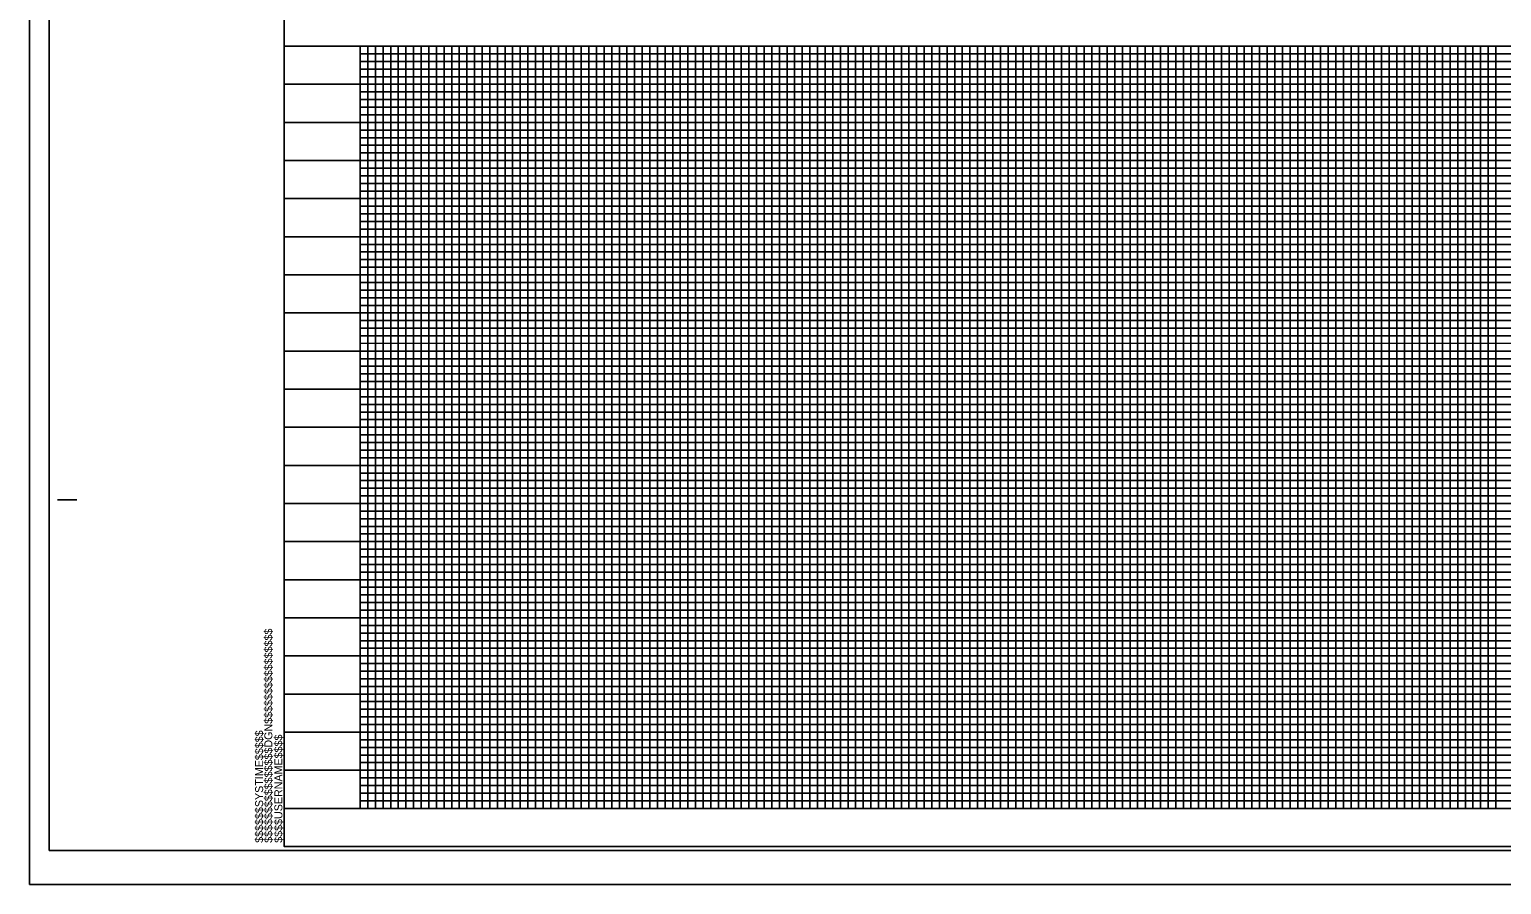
# Model space of a CAD drawing. Extents: x 1648862 to 1650739, y 844691 to 845791.
# Drawn here: x 1648862 to 1649828, y 844691 to 845252 of the extents above; entities that cross this region are included whole.
import ezdxf

# ---------------------------------------------------------------- set-up
doc = ezdxf.new("R2010")
doc.units = 0
for name, color, linetype in [('Prop Conc Barrier Transition Section', 7, 'Continuous'), ('Prop Conc Barrier Variable Height', 7, 'Continuous'), ('Prop Conc Expressway Gutter', 7, 'Continuous'), ('Prop DGN Element Guardrail', 7, 'Continuous'), ('Prop Dimension', 7, 'Continuous'), ('Prop Dimension Text', 7, 'Continuous'), ('Prop Easement Construction', 7, 'Continuous'), ('Prop Easement Construction Station Offsets', 7, 'Continuous')]:
    doc.layers.add(name, color=color, linetype=linetype)

msp = doc.modelspace()

# ---------------------------------------------------------------- linework, layer by layer
at = {"layer": 'Prop Conc Barrier Transition Section'}
msp.add_lwpolyline([(1648862.28, 844691.02), (1650546.28, 844691.02), (1650546.28, 845791.02), (1648862.28, 845791.02)], close=True, dxfattribs=at)
at = {"layer": 'Prop Conc Barrier Variable Height'}
msp.add_lwpolyline([(1649079.28, 845241.02), (1650479.28, 845241.02), (1650479.28, 844741.02), (1649079.28, 844741.02)], close=True, dxfattribs=at)
at = {"layer": 'Prop Conc Expressway Gutter'}
for p, q in [((1649079.28, 845236.02), (1650479.28, 845236.02)), ((1650479.28, 845231.02), (1649079.28, 845231.02)), ((1649079.28, 845226.02), (1650479.28, 845226.02)), ((1650479.28, 845221.02), (1649079.28, 845221.02)), ((1649079.28, 845211.02), (1650479.28, 845211.02)), ((1650479.28, 845206.02), (1649079.28, 845206.02)), ((1649079.28, 845201.02), (1650479.28, 845201.02)), ((1650479.28, 845196.02), (1649079.28, 845196.02)), ((1649079.28, 845186.02), (1650479.28, 845186.02)), ((1650479.28, 845181.02), (1649079.28, 845181.02)), ((1649079.28, 845176.02), (1650479.28, 845176.02)), ((1650479.28, 845171.02), (1649079.28, 845171.02)), ((1649079.28, 845161.02), (1650479.28, 845161.02)), ((1650479.28, 845156.02), (1649079.28, 845156.02)), ((1649079.28, 845151.02), (1650479.28, 845151.02)), ((1650479.28, 845146.02), (1649079.28, 845146.02)), ((1649079.28, 845136.02), (1650479.28, 845136.02)), ((1650479.28, 845131.02), (1649079.28, 845131.02)), ((1649079.28, 845126.02), (1650479.28, 845126.02)), ((1650479.28, 845121.02), (1649079.28, 845121.02)), ((1649079.28, 845111.02), (1650479.28, 845111.02)), ((1650479.28, 845106.02), (1649079.28, 845106.02)), ((1649079.28, 845101.02), (1650479.28, 845101.02)), ((1650479.28, 845096.02), (1649079.28, 845096.02)), ((1649079.28, 845086.02), (1650479.28, 845086.02)), ((1650479.28, 845081.02), (1649079.28, 845081.02)), ((1649079.28, 845076.02), (1650479.28, 845076.02)), ((1650479.28, 845071.02), (1649079.28, 845071.02)), ((1649079.28, 845061.02), (1650479.28, 845061.02)), ((1650479.28, 845056.02), (1649079.28, 845056.02)), ((1649079.28, 845051.02), (1650479.28, 845051.02)), ((1650479.28, 845046.02), (1649079.28, 845046.17)), ((1649079.28, 845036.02), (1650479.28, 845036.02)), ((1650479.28, 845031.02), (1649079.28, 845031.02)), ((1649079.28, 845026.02), (1650479.28, 845026.02)), ((1650479.28, 845021.02), (1649079.28, 845021.02)), ((1649079.28, 845011.02), (1650479.28, 845011.02)), ((1650479.28, 845006.02), (1649079.28, 845006.02)), ((1649079.28, 845001.02), (1650479.28, 845001.02)), ((1650479.28, 844996.02), (1649079.28, 844996.02)), ((1649079.28, 844986.02), (1650479.28, 844986.02)), ((1650479.28, 844981.02), (1649079.28, 844981.02)), ((1649079.28, 844976.02), (1650479.28, 844976.02)), ((1650479.28, 844971.02), (1649079.28, 844971.02)), ((1649079.28, 844961.02), (1650479.28, 844961.02)), ((1650479.28, 844956.02), (1649079.28, 844956.02)), ((1649079.28, 844951.02), (1650479.28, 844951.02)), ((1650479.28, 844946.02), (1649079.28, 844946.02)), ((1649079.28, 844936.02), (1650479.28, 844936.02)), ((1650479.28, 844931.02), (1649079.28, 844931.02)), ((1649079.28, 844926.02), (1650479.28, 844926.02)), ((1650479.28, 844921.02), (1649079.28, 844921.02)), ((1649079.28, 844911.02), (1650479.28, 844911.02)), ((1650479.28, 844906.02), (1649079.28, 844906.02)), ((1649079.28, 844901.02), (1650479.28, 844901.02)), ((1650479.28, 844896.02), (1649079.28, 844896.02)), ((1649079.28, 844886.02), (1650479.28, 844886.02)), ((1650479.28, 844881.02), (1649079.28, 844881.02)), ((1649079.28, 844876.02), (1650479.28, 844876.02)), ((1650479.28, 844871.02), (1649079.28, 844871.02)), ((1649079.28, 844861.02), (1650479.28, 844861.02)), ((1650479.28, 844856.02), (1649079.28, 844856.02)), ((1649079.28, 844851.02), (1650479.28, 844851.02)), ((1650479.28, 844846.02), (1649079.28, 844846.02)), ((1649079.28, 844836.02), (1650479.28, 844836.02)), ((1650479.28, 844831.02), (1649079.28, 844831.02)), ((1649079.28, 844826.02), (1650479.28, 844826.02)), ((1650479.28, 844821.02), (1649079.28, 844821.02)), ((1649079.28, 844811.02), (1650479.28, 844811.02)), ((1650479.28, 844806.02), (1649079.28, 844806.02)), ((1649079.28, 844801.02), (1650479.28, 844801.02)), ((1650479.28, 844796.02), (1649079.28, 844796.02)), ((1649079.28, 844786.02), (1650479.28, 844786.02)), ((1650479.28, 844781.02), (1649079.28, 844781.02)), ((1649079.28, 844776.02), (1650479.28, 844776.02)), ((1650479.28, 844771.02), (1649079.28, 844771.02)), ((1649079.28, 844761.02), (1650479.28, 844761.02)), ((1650479.28, 844756.02), (1649079.28, 844756.02)), ((1649079.28, 844751.02), (1650479.28, 844751.02)), ((1649079.28, 844746.02), (1650479.28, 844746.02))]:
    msp.add_line(p, q, dxfattribs=at)
for points in [[(1649079.28, 845241.02), (1649084.28, 845241.02), (1649084.28, 844741.02), (1649089.28, 844741.02), (1649089.28, 845241.02), (1649094.28, 845241.02), (1649094.28, 844741.02), (1649099.28, 844741.02), (1649099.28, 845241.02), (1649109.28, 845241.02), (1649109.28, 844741.02), (1649114.28, 844741.02), (1649114.28, 845241.02), (1649119.28, 845241.02), (1649119.28, 844741.02), (1649124.28, 844741.02), (1649134.28, 844741.02), (1649139.28, 844741.02), (1649139.28, 845241.02), (1649144.28, 845241.02), (1649144.28, 844741.02), (1649149.28, 844741.02), (1649149.28, 845241.02), (1649159.28, 845241.02), (1649159.28, 844741.02), (1649164.28, 844741.02), (1649164.28, 845241.02), (1649169.28, 845241.02), (1649169.28, 844741.02), (1649174.28, 844741.02), (1649174.28, 845241.02), (1649184.28, 845241.02), (1649184.28, 844741.02), (1649189.28, 844741.02), (1649189.28, 845241.02), (1649194.28, 845241.02), (1649194.28, 844741.02), (1649199.28, 844741.02), (1649199.28, 845241.02), (1649209.28, 845241.02), (1649209.28, 844741.02), (1649214.28, 844741.02), (1649214.28, 845241.02), (1649219.28, 845241.02), (1649219.28, 844741.02), (1649224.28, 844741.02), (1649224.28, 845241.02), (1649234.28, 845241.02), (1649234.28, 844741.02), (1649239.28, 844741.02), (1649239.28, 845241.02), (1649244.28, 845241.02), (1649244.28, 844741.02), (1649249.28, 844741.02), (1649249.28, 845241.02), (1649259.28, 845241.02), (1649259.28, 844741.02), (1649264.28, 844741.02), (1649264.28, 845241.02), (1649269.28, 845241.02), (1649269.28, 844741.02), (1649274.28, 844741.02), (1649274.28, 845241.02), (1649284.28, 845241.02), (1649284.28, 844741.02), (1649289.28, 844741.02), (1649289.28, 845241.02), (1649294.28, 845241.02), (1649294.28, 844741.02)], [(1649124.28, 844741.02), (1649124.28, 845241.02), (1649134.28, 845241.02), (1649134.28, 844741.02)], [(1649294.28, 844741.02), (1649299.28, 844741.02), (1649299.28, 845241.02), (1649309.28, 845241.02), (1649309.28, 844741.02), (1649314.28, 844741.02), (1649314.28, 845241.02), (1649319.28, 845241.02), (1649319.28, 844741.02), (1649324.28, 844741.02), (1649324.28, 845241.02), (1649334.28, 845241.02), (1649334.28, 844741.02), (1649339.28, 844741.02), (1649339.28, 845241.02), (1649344.28, 845241.02), (1649344.28, 844741.02), (1649349.28, 844741.02), (1649349.28, 845241.02), (1649359.28, 845241.02), (1649359.28, 844741.02), (1649364.28, 844741.02), (1649364.28, 845241.02), (1649369.28, 845241.02), (1649369.28, 844741.02), (1649374.28, 844741.02), (1649374.28, 845241.02), (1649384.28, 845241.02), (1649384.28, 844741.02), (1649389.28, 844741.02), (1649389.28, 845241.02), (1649394.28, 845241.02), (1649394.28, 844741.02), (1649399.28, 844741.02), (1649399.28, 845241.02), (1649409.28, 845241.02), (1649409.28, 844741.02), (1649414.28, 844741.02), (1649414.28, 845241.02), (1649419.28, 845241.02), (1649419.28, 844741.02), (1649424.28, 844741.02), (1649424.28, 845241.02), (1649434.28, 845241.02), (1649434.28, 844741.02), (1649439.28, 844741.02), (1649439.28, 845241.02), (1649444.28, 845241.02), (1649444.28, 844741.02), (1649449.28, 844741.02), (1649449.28, 845241.02), (1649459.28, 845241.02), (1649459.28, 844741.02), (1649464.28, 844741.02), (1649464.28, 845241.02), (1649469.28, 845241.02), (1649469.28, 844741.02), (1649474.28, 844741.02), (1649474.28, 845241.02), (1649484.28, 845241.02), (1649484.28, 844741.02), (1649489.28, 844741.02), (1649489.28, 845241.02), (1649494.28, 845241.02), (1649494.28, 844741.02), (1649499.28, 844741.02), (1649499.28, 845241.02), (1649509.28, 845241.02), (1649509.28, 844741.02), (1649514.28, 844741.02), (1649514.28, 845241.02), (1649519.28, 845241.02), (1649519.28, 844741.02), (1649524.28, 844741.02), (1649524.28, 845241.02), (1649534.28, 845241.02), (1649534.28, 844741.02), (1649539.28, 844741.02), (1649539.28, 845241.02), (1649544.28, 845241.02), (1649544.28, 844741.02), (1649549.28, 844741.02), (1649549.28, 845241.02), (1649559.28, 845241.02), (1649559.28, 844741.02), (1649564.28, 844741.02), (1649564.28, 845241.02), (1649569.28, 845241.02), (1649569.28, 844741.02), (1649574.28, 844741.02), (1649574.28, 845241.02), (1649584.28, 845241.02), (1649584.28, 844741.02), (1649589.28, 844741.02), (1649589.28, 845241.02), (1649594.28, 845241.02), (1649594.28, 844741.02), (1649599.28, 844741.02), (1649599.28, 845241.02), (1649609.28, 845241.02)], [(1649609.28, 845241.02), (1649609.28, 844741.02), (1649614.28, 844741.02), (1649614.28, 845241.02), (1649619.28, 845241.02), (1649619.28, 844741.02), (1649624.28, 844741.02), (1649624.28, 845241.02), (1649634.28, 845241.02), (1649634.28, 844741.02), (1649639.28, 844741.02), (1649639.28, 845241.02), (1649644.28, 845241.02), (1649644.28, 844741.02), (1649649.28, 844741.02), (1649649.28, 845241.02), (1649659.28, 845241.02), (1649659.28, 844741.02), (1649664.28, 844741.02), (1649664.28, 845241.02), (1649669.28, 845241.02), (1649669.28, 844741.02), (1649674.28, 844741.02), (1649674.28, 845241.02), (1649684.28, 845241.02), (1649684.28, 844741.02), (1649689.28, 844741.02), (1649689.28, 845241.02), (1649694.28, 845241.02), (1649694.28, 844741.02), (1649699.28, 844741.02), (1649699.28, 845241.02), (1649709.28, 845241.02), (1649709.28, 844741.02), (1649714.28, 844741.02), (1649714.28, 845241.02), (1649719.28, 845241.02), (1649719.28, 844741.02), (1649724.28, 844741.02), (1649724.28, 845241.02), (1649734.28, 845241.02), (1649734.28, 844741.02), (1649734.28, 844741.02), (1649739.28, 844741.02), (1649739.28, 845241.02), (1649744.28, 845241.02), (1649744.28, 844741.02), (1649749.28, 844741.02), (1649749.28, 845241.02), (1649759.28, 845241.02), (1649759.28, 844741.02), (1649764.28, 844741.02), (1649764.28, 845241.02), (1649769.28, 845241.02), (1649769.28, 844741.02), (1649774.28, 844741.02), (1649774.28, 845241.02), (1649784.28, 845241.02), (1649784.28, 844741.02), (1649789.28, 844741.02), (1649789.28, 845241.02), (1649794.28, 845241.02), (1649794.28, 844741.02), (1649799.28, 844741.02), (1649799.28, 845241.02), (1649809.28, 845241.02), (1649809.28, 844741.02), (1649814.28, 844741.02), (1649814.28, 845241.02), (1649819.28, 845241.02), (1649819.28, 844741.02), (1649824.28, 844741.02), (1649824.28, 845241.02), (1649834.28, 845241.02)]]:
    msp.add_lwpolyline(points, dxfattribs=at)
at = {"layer": 'Prop DGN Element Guardrail'}
for p, q in [((1649029.28, 845241.02), (1650529.28, 845241.02)), ((1648880.78, 844943.52), (1648893.28, 844943.52)), ((1650529.28, 844741.02), (1649029.28, 844741.02)), ((1649029.28, 844716.02), (1650529.28, 844716.02)), ((1649029.28, 844716.02), (1649029.28, 844716.02)), ((1649029.28, 844716.02), (1649029.28, 844716.02)), ((1649029.28, 844716.02), (1649029.28, 844716.02)), ((1649029.28, 844716.02), (1649029.28, 844716.02)), ((1649029.28, 844716.02), (1649029.28, 844716.02)), ((1649029.28, 844716.02), (1649029.28, 844716.02)), ((1649029.28, 844716.02), (1649029.28, 844716.02))]:
    msp.add_line(p, q, dxfattribs=at)
msp.add_lwpolyline([(1650529.28, 845766.02), (1649029.28, 845766.02), (1649029.28, 844716.02), (1650529.28, 844716.02)], close=True, dxfattribs=at)
msp.add_lwpolyline([(1649066.78, 844716.02), (1649066.78, 844716.02)], dxfattribs=at)
at = {"layer": 'Prop Dimension'}
for p, q in [((1649529.28, 845241.02), (1649579.28, 845241.02)), ((1649629.28, 845241.02), (1649679.28, 845241.02)), ((1649729.28, 845241.02), (1649779.28, 845241.02)), ((1649029.28, 844741.02), (1649029.28, 844741.02))]:
    msp.add_line(p, q, dxfattribs=at)
for points in [[(1649079.28, 845241.02), (1649079.28, 844741.02), (1649129.28, 844741.02), (1649129.28, 845241.02), (1649179.28, 845241.02), (1649179.28, 844741.02), (1649229.28, 844741.02), (1649229.28, 845241.02), (1649279.28, 845241.02), (1649279.28, 844741.02), (1649329.28, 844741.02), (1649329.28, 845241.02), (1649379.28, 845241.02), (1649379.28, 844741.02), (1649429.28, 844741.02), (1649429.28, 845241.02), (1649479.28, 845241.02), (1649479.28, 844741.02), (1649529.28, 844741.02), (1649529.28, 845241.02), (1649579.28, 845241.02), (1649579.28, 844741.02), (1649629.28, 844741.02), (1649629.28, 845241.02), (1649679.28, 845241.02), (1649679.28, 844741.02), (1649729.28, 844741.02), (1649729.28, 845241.02), (1649779.28, 845241.02), (1649779.28, 844741.02), (1649829.28, 844741.02)], [(1650529.28, 845191.02), (1649029.28, 845191.02)], [(1650529.28, 845141.02), (1649029.28, 845141.02), (1649029.28, 845091.02), (1650529.28, 845091.02)], [(1650529.28, 845041.02), (1649029.28, 845041.02), (1649029.28, 844991.02), (1650529.28, 844991.02)], [(1650529.28, 844941.02), (1649029.28, 844941.02), (1649029.28, 844891.02), (1650529.28, 844891.02)], [(1650529.28, 844841.02), (1649029.28, 844841.02), (1649029.28, 844841.02), (1649029.28, 844791.02), (1650529.28, 844791.02)], [(1650529.28, 844741.02), (1649029.28, 844741.02)]]:
    msp.add_lwpolyline(points, dxfattribs=at)
at = {"layer": 'Prop Dimension Text'}
for points in [[(1649054.28, 845241.02), (1649104.28, 845241.02), (1649104.28, 844741.02), (1649154.28, 844741.02), (1649154.28, 845241.02), (1649204.28, 845241.02), (1649204.28, 844741.02), (1649254.28, 844741.02), (1649254.28, 845241.02), (1649304.28, 845241.02), (1649304.28, 844741.02), (1649354.28, 844741.02), (1649354.28, 845241.02), (1649404.28, 845241.02), (1649404.28, 844741.02), (1649454.28, 844741.02), (1649454.28, 845241.02), (1649504.28, 845241.02), (1649504.28, 844741.02), (1649554.28, 844741.02), (1649554.28, 845241.02), (1649604.28, 845241.02), (1649604.28, 844741.02), (1649654.28, 844741.02), (1649654.28, 844741.02), (1649654.28, 845241.02), (1649704.28, 845241.02), (1649704.28, 844741.02), (1649754.28, 844741.02), (1649754.28, 845241.02), (1649804.28, 845241.02), (1649804.28, 844741.02), (1649854.28, 844741.02)], [(1649029.28, 845216.02), (1650529.28, 845216.02)], [(1650529.28, 845166.02), (1649029.28, 845166.02), (1649029.28, 845116.02), (1650529.28, 845116.02)], [(1650529.28, 845066.02), (1649029.28, 845066.02), (1649029.28, 845016.02), (1650529.28, 845016.02)], [(1650529.28, 844966.02), (1649029.28, 844966.02), (1649029.28, 844916.02), (1650529.28, 844916.02)], [(1650529.28, 844866.02), (1649029.28, 844866.02), (1649029.28, 844816.02), (1650529.28, 844816.02)], [(1650529.28, 844766.02), (1649029.28, 844766.02)]]:
    msp.add_lwpolyline(points, dxfattribs=at)
at = {"layer": 'Prop Easement Construction'}
msp.add_lwpolyline([(1648875.28, 844713.47), (1650541.78, 844713.47), (1650541.78, 845768.57), (1648875.28, 845768.57)], close=True, dxfattribs=at)
at = {"layer": 'Prop Easement Construction Station Offsets'}
for p, q in [((1649029.28, 845241.02), (1650529.17, 845241.02)), ((1649079.28, 845241.02), (1649079.28, 844741.02)), ((1649129.28, 845241.02), (1649129.28, 844741.02)), ((1649179.28, 845241.02), (1649179.28, 844741.02)), ((1649229.28, 845241.02), (1649229.28, 844741.02)), ((1649279.28, 845241.02), (1649279.28, 844741.02)), ((1649329.28, 845241.02), (1649329.28, 844741.02)), ((1649379.28, 845241.02), (1649379.28, 844741.02)), ((1649429.28, 845241.02), (1649429.28, 844741.02)), ((1649479.28, 845241.02), (1649479.28, 844741.02)), ((1649529.28, 845241.02), (1649529.28, 844741.02)), ((1649579.28, 845241.02), (1649579.28, 844741.02)), ((1649629.28, 845241.02), (1649629.28, 844741.02)), ((1649679.28, 845241.02), (1649679.28, 844741.02)), ((1649729.28, 845241.02), (1649729.28, 844741.02)), ((1649779.28, 845241.02), (1649779.28, 844741.02)), ((1649029.28, 845191.02), (1650529.17, 845191.02)), ((1649029.28, 845141.02), (1650529.17, 845141.02)), ((1649029.28, 845091.02), (1650529.17, 845091.02)), ((1649029.28, 845041.02), (1650529.17, 845041.02)), ((1649029.28, 844991.02), (1650529.17, 844991.02)), ((1649029.28, 844941.02), (1650529.17, 844941.02)), ((1649029.28, 844891.02), (1650529.17, 844891.02)), ((1649029.28, 844841.02), (1650529.17, 844841.02)), ((1649029.28, 844791.02), (1650529.17, 844791.02))]:
    msp.add_line(p, q, dxfattribs=at)

# ---------------------------------------------------------------- texts
at = {"layer": 'Prop DGN Element Guardrail'}
for s, p in [('$$$$$$$$$$$$$$$$DGN$$$$$$$$$$$$$$$$', (1649021.64, 844718.4)), ('$$$$$$SYSTIME$$$$$', (1649015.59, 844718.4)), ('$$$$USERNAME$$$$', (1649028.22, 844718.41))]:
    msp.add_text(s, height=5.25, rotation=90, dxfattribs=at).set_placement(p)

doc.saveas('drawing.dxf')
